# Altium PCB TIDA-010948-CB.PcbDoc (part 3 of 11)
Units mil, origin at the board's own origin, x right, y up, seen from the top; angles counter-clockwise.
Board outline 8100 x 8400 mil, 8 copper layers (L01 - TOP, L02 - GND, L03 - SIG, L04 - GND, L05 - PWR, L06 - SIG, L07 - GND, L08 - BOTTOM), stack 59.656 mil thick; 711 components, 572 nets, 2646 pads, 1325 vias.
Unrouted connection lines stored in the file: 988.
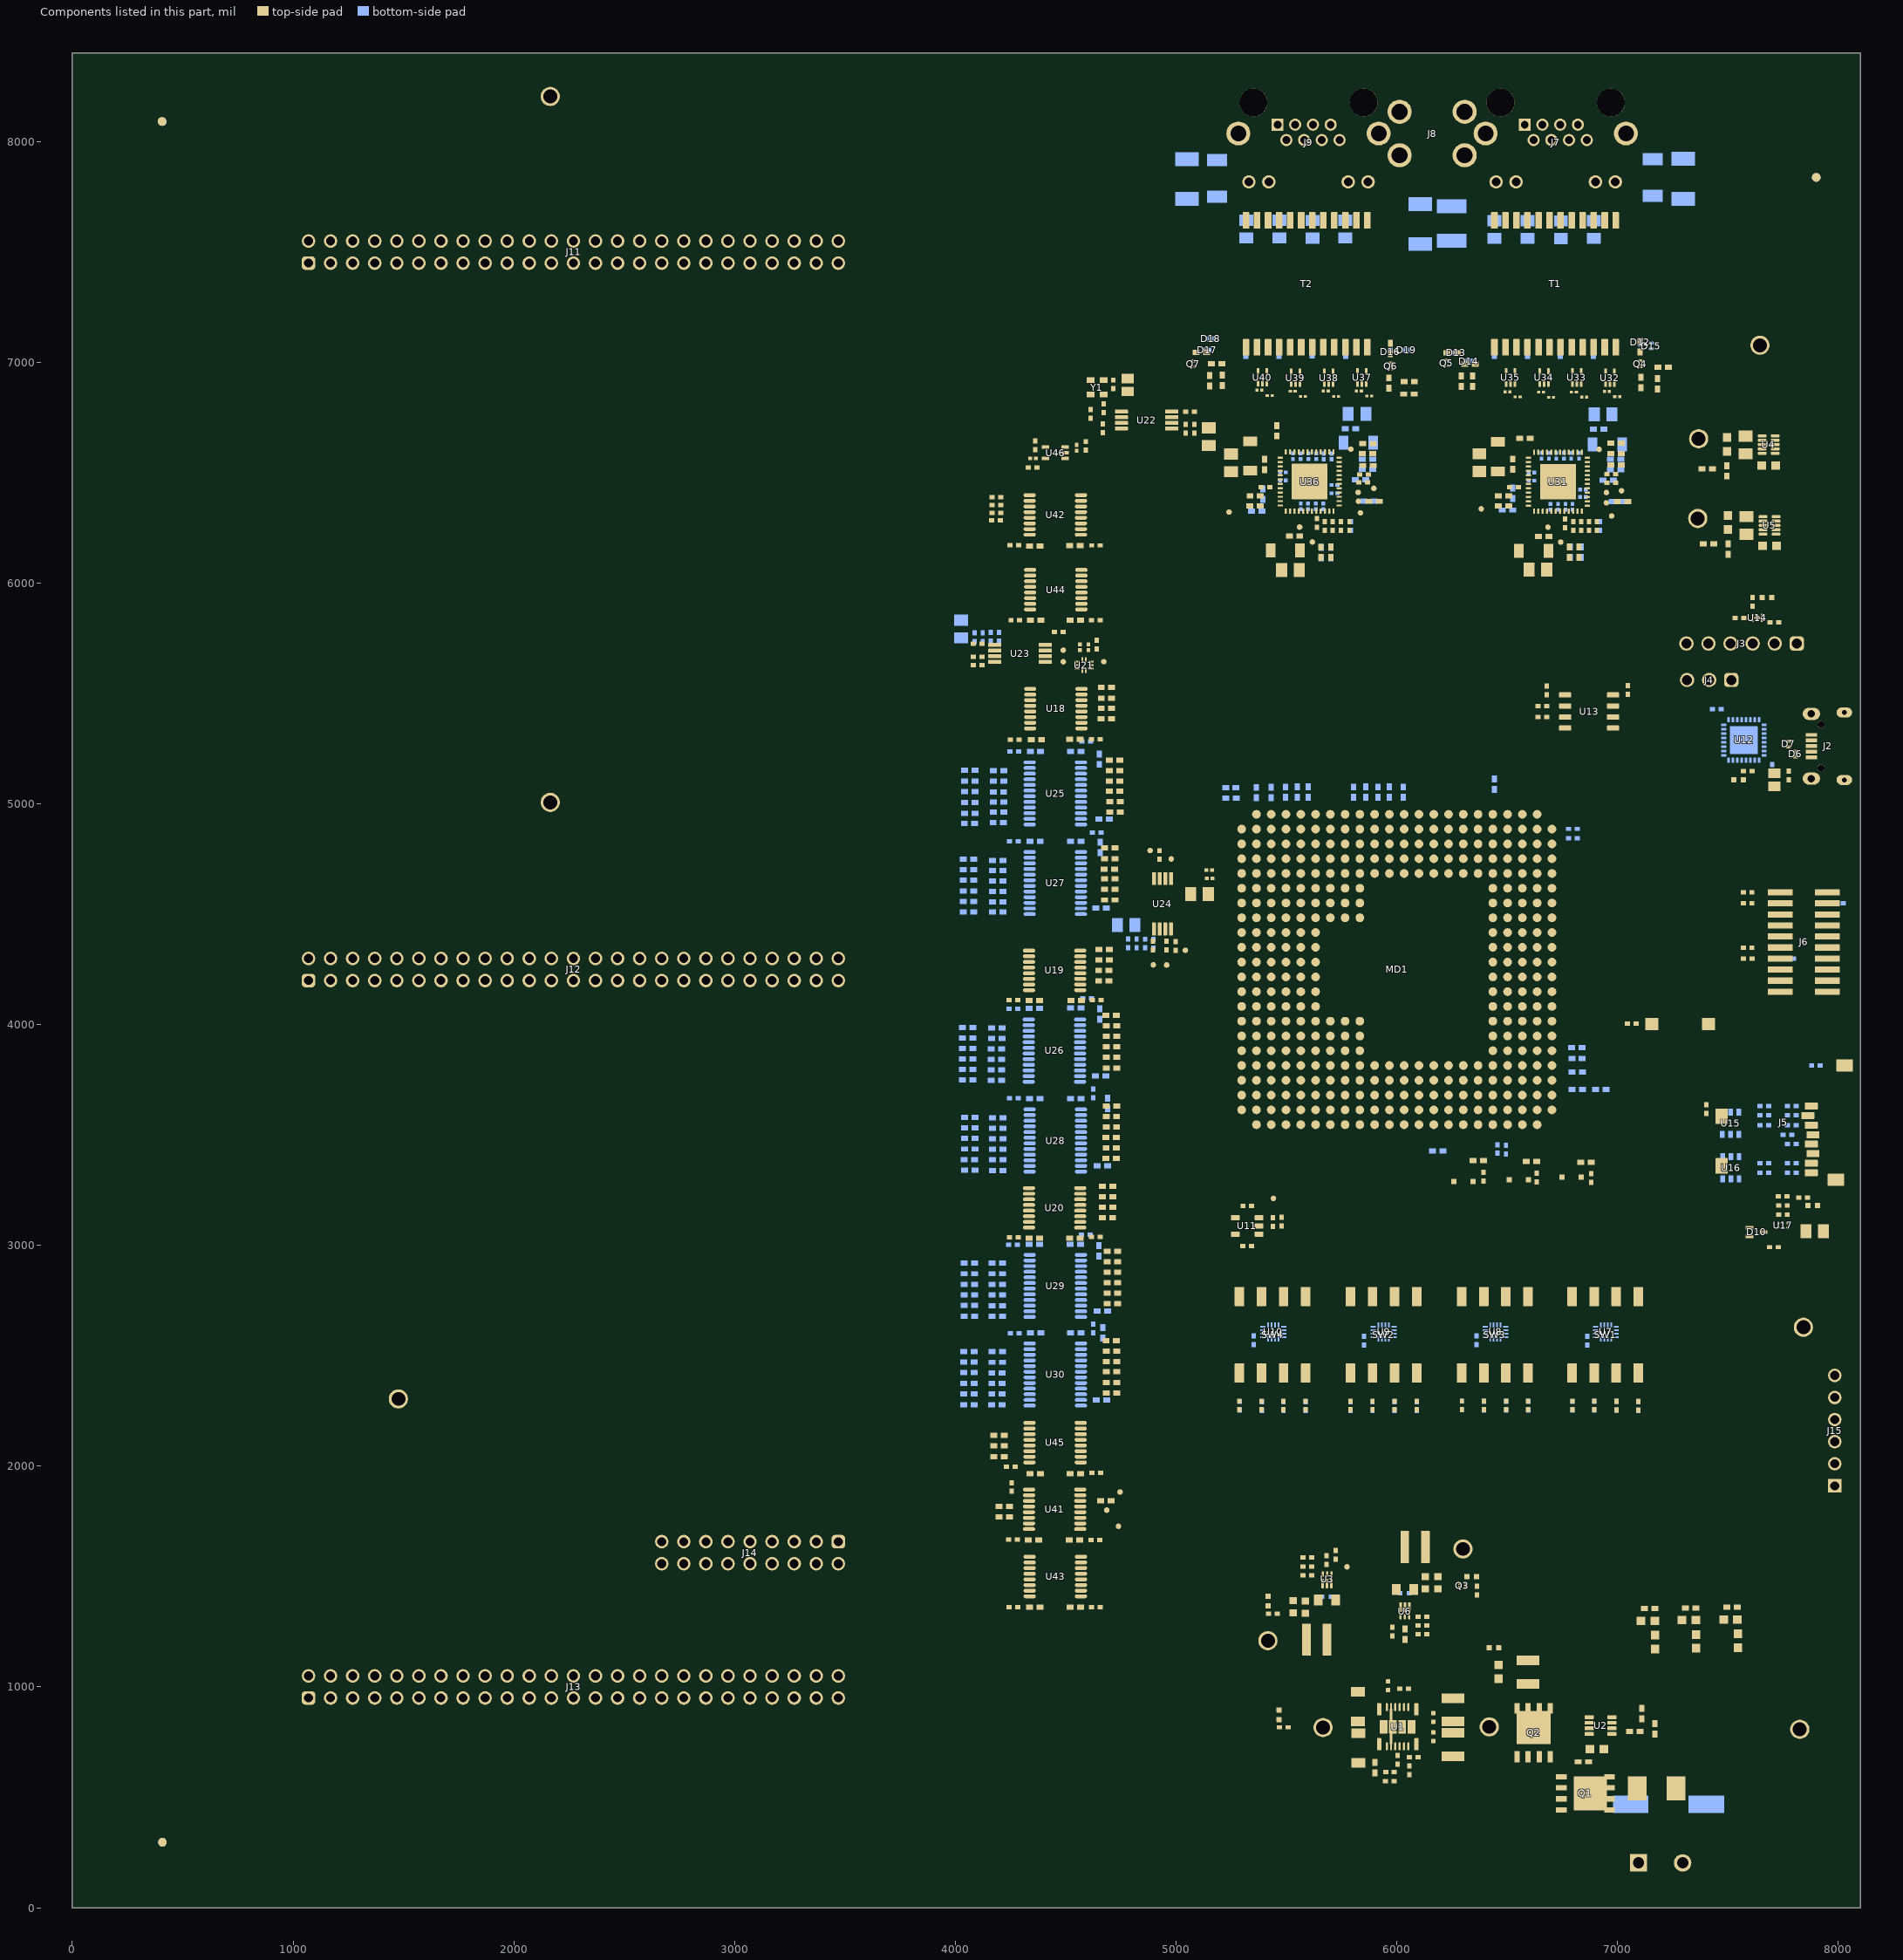
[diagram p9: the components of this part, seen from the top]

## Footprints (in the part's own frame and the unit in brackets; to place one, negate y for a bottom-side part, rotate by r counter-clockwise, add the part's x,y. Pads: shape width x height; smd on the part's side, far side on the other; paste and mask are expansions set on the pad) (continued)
0201L [mm] "Data from Kemet datasheet CC101_COM dated 7/28/11"
  rect 0.36x0.32 smd mask+0.048: 1(-0.28,0) 2(0.28,0)
  body extent -0.31,-0.16 0.31,0.16, height 0.26
0402 [mm] "0402 from SM-752 data"
  rect 0.8x0.6 smd: 1(-0.6,0) 2(0.6,0)
  silkscreen extent -1.22,-0.52 1.22,0.52, body extent -0.55,-0.3 0.55,0.3, height 0.6
0402L [mm] "0402 from SM-752 data"
  rect 0.6x0.5 smd: 1(-0.5,0) 2(0.5,0)
  body extent -0.55,-0.3 0.55,0.3, height 0.6
0603 [mm] "0603 from SM-752 data"
  rect 1x0.95 smd: 1(-0.8,0) 2(0.8,0)
  silkscreen extent -1.52,-0.69 1.52,0.69, body extent -0.87,-0.47 0.87,0.47, height 1
0603L [mm] "0603 from SM-752 data"
  rect 0.8x0.85 smd: 1(-0.7,0) 2(0.7,0)
  silkscreen extent -0.07,-0.33 0.07,0.33, body extent -0.87,-0.47 0.87,0.47, height 1
0805_HV [mil] "0805 with 30mil clearance between pads"
  rect 50x63 smd: 1(-40,0) 2(40,0)
  silkscreen extent -74,-40 74,40, body extent -43,-29 43,29, height 57
0805_HV1 [mm] "Custom footprint based on analyzing multiple manufacturer recommendations"
  rrect10% 1x1.25 smd: 1(-1,0) 2(1,0)
  silkscreen extent -0.2,-0.75 0.2,0.75, body extent -1.1,-0.72 1.1,0.73, height 1.45
0805L [mm] "0805 from SM-752 data"
  rect 1.1x1.4 smd: 1(-0.75,0) 2(0.75,0)
  body extent -1.1,-0.72 1.1,0.72, height 1.45
1206_190 [mm] "1206_190"
  rect 1.1x1.6 smd: 1(-1.7,0) 2(1.7,0)
  silkscreen extent -0.9,-1 0.9,1, body extent -1.75,-0.95 1.75,0.95, height 1.9
1210_270L [mm] "1210"
  rect 1.1x2.6 smd: 1(-1.35,0) 2(1.35,0)
  silkscreen extent -0.4,-1.2 0.4,1.2, body extent -1.7,-1.35 1.7,1.35, height 2.7
1808 [mm] "Chip Capacitor, Body 4.6x2.0mm, IPC Medium Density"
  rect 1.4x2.3 smd: 1(-2.1,0) 2(2.1,0)
  silkscreen extent -3.1,-1.45 3.1,1.45, body extent -2.47,-1.2 2.47,1.2, height 2.03
1812 [mm]
  rect 1.6x3.4 smd: 1(-2,0) 2(2,0)
  silkscreen extent -0.8,-1.6 0.8,1.6, body extent -2.4,-1.7 2.4,1.7, height 1.35
2010 [mm] "Chip Capacitor, Body 5.08x2.54mm, IPC Medium Density"
  rect 1.6x2.7 smd: 1(-2.3,0) 2(2.3,0)
  silkscreen extent -3.42,-1.65 3.42,1.65, body extent -2.73,-1.45 2.73,1.45, height 1.66
D0008B_HV [mm] "SOIC, 8-Leads, Body 4.9x3.9mm, Pitch 1.27mm, HV / Isolation option"
  rrect17% 1.4x0.6 smd: 1(-2.75,1.905) 2(-2.75,0.635) 3(-2.75,-0.635) 4(-2.75,-1.905) 5(2.75,-1.905) 6(2.75,-0.635) 7(2.75,0.635) 8(2.75,1.905)
  silkscreen extent -3.3,-2.5 0.9,2.5, body extent -3,-2.45 3,2.45, height 1.63
DBV0005A_N [mm] "SOT23, 5-Leads, Body 2.9x1.6mm, Pitch 0.95mm, Lead Span 2.8mm, IPC Medium Density"
  rrect17% 1x0.6 smd: 1(-1.375,0.95) 2(-1.375,0) 3(-1.375,-0.95) 4(1.375,-0.95) 5(1.375,0.95)
  silkscreen extent -1.63,-1.55 0.38,1.55, body extent -1.42,-1.46 1.42,1.46, height 1.09
DBV0006A_L [mm] "SOT23, 6-Leads, Body 2.9x1.6mm, Pitch 0.95mm, Lead Span 2.8mm, IPC High Density"
  rrect18% 0.8x0.55 smd: 1(-1.275,0.95) 2(-1.275,0) 3(-1.275,-0.95) 4(1.275,-0.95) 5(1.275,0) 6(1.275,0.95)
  silkscreen extent -1.55,-1.53 0.55,1.53, body extent -1.42,-1.46 1.42,1.46, height 1.12
DCK0005A_N [mm] "SOT353, 5-Leads, Body 2x1.3mm, Pitch 0.65mm, Lead Span 2.1mm, IPC Medium Density"
  rrect25% 0.85x0.4 smd: 1(-1.125,0.65) 2(-1.125,0) 3(-1.125,-0.65) 4(1.125,-0.65) 5(1.125,0.65)
  silkscreen extent -1.48,-1.02 0.55,1.1, body extent -1.14,-1 1.14,1, height 0.95
DDF0008A-MFG [mm]
  rrect22% 1.05x0.45 smd paste+0 mask+0: 1(-1.3,0.975) 2(-1.3,0.325) 3(-1.3,-0.325) 4(-1.3,-0.975) 5(1.3,-0.975) 6(1.3,-0.325) 7(1.3,0.325) 8(1.3,0.975)
  silkscreen extent -2.5,-1.48 0.4,1.48, body extent -1.92,-1.73 1.92,1.73, height 0.25
DLF0004A-MFG [mm]
  rrect15% 0.9x0.65 smd paste-1000 mask+0: 1(-0.75,0.825) 2(-0.75,-0.825) 3(0.75,-0.825) 4(0.75,0.825)
  silkscreen extent -1.87,-0.13 1.05,0.95, body extent -1.3,-1.4 1.3,1.4, height 0.25
DMQ0006A [mm] "6-pin VSON"
  rrect40% 0.6x0.25 smd paste+0: 1(-0.65,0.5) 2(-0.65,0) 3(-0.65,-0.5)
  rrect67% 1.1x0.3 smd paste-0.15 mask-0.05: 4(0.45,-0.5) 5(0.45,0) 6(0.45,0.5)
  rrect50% 0.85x0.2 on Top Paste: 4(0.525,-0.5) 5(0.525,0) 6(0.525,0.5)
  silkscreen extent -0.75,-0.9 0.75,0.9, body extent -0.75,-0.75 0.75,0.75, height 1
DPY0002A#1 [mm] "X1SON-2"
  rrect57% 0.35x0.6 smd paste-0.5 mask-0.05: 1(-0.325,0) 2(0.325,0)
  rrect33% 0.3x0.5 on Top Paste: 1S(-0.35,0) 2S(0.35,0)
  silkscreen extent -0.85,-0.02 -0.8,0.03, body extent -0.5,-0.3 0.5,0.3, height 0.45
DPY0002A#2 [mm] "X1SON-2"
  rrect57% 0.35x0.6 smd paste-0.5 mask-0.05: 1(-0.325,0) 2(0.325,0)
  rrect33% 0.3x0.5 on Bottom Paste: 1S(-0.35,0) 2S(0.35,0)
  silkscreen extent -0.85,-0.02 -0.8,0.03, body extent -0.5,-0.3 0.5,0.3, height 0.45
DQN0004A [mm] "SON, 0.65mm pitch"
  rect 0.25x0.31 smd paste-1 mask-0.31: 1(-0.535,0.325) 2(-0.535,-0.325) 3(0.535,-0.325) 4(0.535,0.325)
  rect 0.58x0.58 smd rot 45 paste-0.065 mask-0.05: 5(0,0)
  L01 - TOP region: -0.66,-0.48 -0.2,-0.48 -0.2,-0.379 -0.409,-0.17 -0.66,-0.17
  L01 - TOP region: 0.66,-0.48 0.2,-0.48 0.2,-0.379 0.409,-0.17 0.66,-0.17
  L01 - TOP region: 0.66,0.48 0.2,0.48 0.2,0.379 0.409,0.17 0.66,0.17
  L01 - TOP region: -0.66,0.48 -0.2,0.48 -0.2,0.379 -0.409,0.17 -0.66,0.17
  silkscreen extent -0.88,-0.7 0.88,0.7, body extent -0.53,-0.53 0.53,0.53, height 0.42
DRL0005A [mm] "SOTFL, 5-Flat Leads, Body 1.2x1.6x0.6mm, Pitch 0.5mm, TI recommended"
  rrect33% 0.67x0.3 smd: 1(-0.74,0.5) 2(-0.74,0) 3(-0.74,-0.5) 4(0.74,-0.5) 5(0.74,0.5)
  silkscreen extent -0.9,-0.95 0.5,0.95, body extent -0.85,-0.85 0.85,0.85, height 0.62
FCC_disclaimer [mil]
Fiducial10-20 [mm]
  round 1 smd mask+0.5: 1(0,0)
  L01 - TOP keep-out circle w1.178: c0,0 r0.5
FP-1888687_HDR2-MFG [mm]
  rrect5% 2x2 hole 1.3 paste-2539.97 mask+0: 1(-2.54,0)
  round 2 hole 1.3 paste-2539.97 mask+0: 2(2.54,0)
  body extent -5.26,-4.92 5.26,4.92, height 0.25
FP-749020011A_SMT_17MM5_14MM2-MFG [mil]
  rrect13% 29.92x75 smd paste+0 mask+0: 1(-275,-287.5) 2(-225,-287.5) 3(-175,-287.5) 4(-125,-287.5) 5(-75,-287.5) 6(-25,-287.5) 7(25,-287.5) 8(75,-287.5) 9(125,-287.5) 10(175,-287.5) 11(225,-287.5) 12(275,-287.5) 13(275,287.5) 14(225,287.5) 15(175,287.5) 16(125,287.5) 17(75,287.5) 18(25,287.5) 19(-25,287.5) 20(-75,287.5) 21(-125,287.5) 22(-175,287.5) 23(-225,287.5) 24(-275,287.5)
  body extent -353,-329 353,329, height 10
FP-418121270804_SMT_SW_11MM1_6MM2-MFG [mm]
  rrect9% 1.1x2.2 smd paste+0 mask+0: 1(-3.81,-4.4) 2(-1.27,-4.4) 3(1.27,-4.4) 4(3.81,-4.4) 5(3.81,4.4) 6(1.27,4.4) 7(-1.27,4.4) 8(-3.81,4.4)
  silkscreen extent -5.65,-6.2 5.65,3.15, body extent -5.75,-5.6 5.75,5.6, height 0.25
FP-615108137421R_CONN_JACK_16MM4_15MM7-MFG [mm]
  rrect7% 1.4x1.4 hole 0.9 paste-2539.97 mask+0: 1(3.57,0.09)
  round 1.4 hole 0.9 paste-2539.97 mask+0: 2(2.55,1.87) 3(1.53,0.09) 4(0.51,1.87) 5(-0.51,0.09) 6(-1.53,1.87) 7(-2.55,0.09) 8(-3.57,1.87)
  round 1.55 hole 1 paste-2539.97 mask+0: 9(6.86,6.68) 10(4.57,6.68) 11(-4.57,6.68) 12(-6.86,6.68)
  round 2.75 hole 1.8 paste-2539.97 mask+0: 13(-8.075,1.11) 14(8.075,1.11)
  round 3.2 hole 3.2 unplated paste-2539.97 mask+0: ""(-6.35,-2.45) ""(6.35,-2.45)
  body extent -11.62,-8.05 11.62,8.05, height 0.25
FP-629105150521_CONN_USB_8MM0_6MM6-MFG [mm]
  rect 0.45x1.3 smd: 1(-1.3,0) 2(-0.65,0) 3(0,0) 4(0.65,0) 5(1.3,0)
  oval 1.4x2 hole 0.85 slot 1.4 at 90 deg: Z1(-3.725,0) Z2(3.725,0)
  oval 1.15x1.8 hole 0.55 slot 1.2 at 90 deg: Z3(3.875,-3.8) Z4(-3.875,-3.8)
  round 0.8 hole 0.8 unplated: ""(-2.5,-1.1) ""(2.5,-1.1)
  silkscreen extent -4,-6.2 4,0.9, body extent -4,-6.25 4,0.35, height 2.67
FP-744383560047HT_1616-MFG [mm]
  rrect10% 0.98x3.7 smd paste+0 mask+0: 1(-1.185,0) 2(1.185,0)
  L01 - TOP keep-out region: -0.695,-1.85 0.695,-1.85 0.695,1.85 -0.695,1.85
  silkscreen extent -2.75,-2.15 2.15,2.15, body extent -2.25,-2.25 2.25,2.25, height 0.25
FP-885012205086_0402-MFG [mm]
  rrect20% 0.5x0.5 smd paste+0 mask+0: 1(-0.5,0) 2(0.5,0)
  silkscreen extent -0.6,-0.63 0.6,0.63, body extent -0.85,-0.45 0.85,0.45, height 0.25
FP-TQMa2434L-AA_LGA366-MFG [mm]
  round 1 smd paste+0 mask+0: A2(-16.15,17.85) A3(-14.45,17.85) A4(-12.75,17.85) A5(-11.05,17.85) A6(-9.35,17.85) A7(-7.65,17.85) A8(-5.95,17.85) A9(-4.25,17.85) A10(-2.55,17.85) A11(-0.85,17.85) A12(0.85,17.85) A13(2.55,17.85) A14(4.25,17.85) A15(5.95,17.85) A16(7.65,17.85) A17(9.35,17.85) A18(11.05,17.85) A19(12.75,17.85) A20(14.45,17.85) A21(16.15,17.85) AA1(-17.85,-16.15) AA2(-16.15,-16.15) AA3(-14.45,-16.15) AA4(-12.75,-16.15) AA5(-11.05,-16.15) AA6(-9.35,-16.15) AA7(-7.65,-16.15) AA8(-5.95,-16.15) AA9(-4.25,-16.15) AA10(-2.55,-16.15) AA11(-0.85,-16.15) AA12(0.85,-16.15) AA13(2.55,-16.15) AA14(4.25,-16.15) AA15(5.95,-16.15) AA16(7.65,-16.15) AA17(9.35,-16.15) AA18(11.05,-16.15) AA19(12.75,-16.15) AA20(14.45,-16.15) AA21(16.15,-16.15) AA22(17.85,-16.15) AB2(-16.15,-17.85) AB3(-14.45,-17.85) AB4(-12.75,-17.85) AB5(-11.05,-17.85) AB6(-9.35,-17.85) AB7(-7.65,-17.85) AB8(-5.95,-17.85) AB9(-4.25,-17.85) AB10(-2.55,-17.85) AB11(-0.85,-17.85) AB12(0.85,-17.85) AB13(2.55,-17.85) AB14(4.25,-17.85) AB15(5.95,-17.85) AB16(7.65,-17.85) AB17(9.35,-17.85) AB18(11.05,-17.85) AB19(12.75,-17.85) AB20(14.45,-17.85) AB21(16.15,-17.85) B1(-17.85,16.15) B2(-16.15,16.15) B3(-14.45,16.15) B4(-12.75,16.15) B5(-11.05,16.15) B6(-9.35,16.15) B7(-7.65,16.15) B8(-5.95,16.15) B9(-4.25,16.15) B10(-2.55,16.15) B11(-0.85,16.15) B12(0.85,16.15) B13(2.55,16.15) B14(4.25,16.15) B15(5.95,16.15) B16(7.65,16.15) B17(9.35,16.15) B18(11.05,16.15) B19(12.75,16.15) B20(14.45,16.15) B21(16.15,16.15) B22(17.85,16.15) C1(-17.85,14.45) C2(-16.15,14.45) C3(-14.45,14.45) C4(-12.75,14.45) C5(-11.05,14.45) C6(-9.35,14.45) C7(-7.65,14.45) C8(-5.95,14.45) C9(-4.25,14.45) C10(-2.55,14.45) C11(-0.85,14.45) C12(0.85,14.45) C13(2.55,14.45) C14(4.25,14.45) C15(5.95,14.45) C16(7.65,14.45) C17(9.35,14.45) C18(11.05,14.45) C19(12.75,14.45) C20(14.45,14.45) C21(16.15,14.45) C22(17.85,14.45) D1(-17.85,12.75) D2(-16.15,12.75) D3(-14.45,12.75) D4(-12.75,12.75) D5(-11.05,12.75) D6(-9.35,12.75) D7(-7.65,12.75) D8(-5.95,12.75) D9(-4.25,12.75) D10(-2.55,12.75) D11(-0.85,12.75) D12(0.85,12.75) D13(2.55,12.75) D14(4.25,12.75) D15(5.95,12.75) D16(7.65,12.75) D17(9.35,12.75) D18(11.05,12.75) D19(12.75,12.75) D20(14.45,12.75) D21(16.15,12.75) D22(17.85,12.75) E1(-17.85,11.05) E2(-16.15,11.05) E3(-14.45,11.05) E4(-12.75,11.05) E5(-11.05,11.05) E6(-9.35,11.05) E7(-7.65,11.05) E8(-5.95,11.05) E9(-4.25,11.05) E10(-2.55,11.05) E11(-0.85,11.05) E12(0.85,11.05) E13(2.55,11.05) E14(4.25,11.05) E15(5.95,11.05) E16(7.65,11.05) E17(9.35,11.05) E18(11.05,11.05) E19(12.75,11.05) E20(14.45,11.05) E21(16.15,11.05) E22(17.85,11.05) F1(-17.85,9.35) F2(-16.15,9.35) F3(-14.45,9.35) F4(-12.75,9.35) F5(-11.05,9.35) F6(-9.35,9.35) F7(-7.65,9.35) F8(-5.95,9.35) F9(-4.25,9.35) F18(11.05,9.35) F19(12.75,9.35) F20(14.45,9.35) F21(16.15,9.35) F22(17.85,9.35) G1(-17.85,7.65) G2(-16.15,7.65) G3(-14.45,7.65) G4(-12.75,7.65) G5(-11.05,7.65) G6(-9.35,7.65) G7(-7.65,7.65) G8(-5.95,7.65) G9(-4.25,7.65) G18(11.05,7.65) G19(12.75,7.65) G20(14.45,7.65) G21(16.15,7.65) G22(17.85,7.65) H1(-17.85,5.95) H2(-16.15,5.95) H3(-14.45,5.95) H4(-12.75,5.95) H5(-11.05,5.95) H6(-9.35,5.95) H7(-7.65,5.95) H8(-5.95,5.95) H9(-4.25,5.95) H18(11.05,5.95) H19(12.75,5.95) H20(14.45,5.95) H21(16.15,5.95) H22(17.85,5.95) J1(-17.85,4.25) J2(-16.15,4.25) J3(-14.45,4.25) J4(-12.75,4.25) J5(-11.05,4.25) J6(-9.35,4.25) J18(11.05,4.25) J19(12.75,4.25) J20(14.45,4.25) J21(16.15,4.25) J22(17.85,4.25) K1(-17.85,2.55) K2(-16.15,2.55) K3(-14.45,2.55) K4(-12.75,2.55) K5(-11.05,2.55) K6(-9.35,2.55) K18(11.05,2.55) K19(12.75,2.55) K20(14.45,2.55) K21(16.15,2.55) K22(17.85,2.55) L1(-17.85,0.85) L2(-16.15,0.85) L3(-14.45,0.85) L4(-12.75,0.85) L5(-11.05,0.85) L6(-9.35,0.85) L18(11.05,0.85) L19(12.75,0.85) L20(14.45,0.85) L21(16.15,0.85) L22(17.85,0.85) M1(-17.85,-0.85) M2(-16.15,-0.85) M3(-14.45,-0.85) M4(-12.75,-0.85) M5(-11.05,-0.85) M6(-9.35,-0.85) M18(11.05,-0.85) M19(12.75,-0.85) M20(14.45,-0.85) M21(16.15,-0.85) M22(17.85,-0.85) N1(-17.85,-2.55) N2(-16.15,-2.55) N3(-14.45,-2.55) N4(-12.75,-2.55) N5(-11.05,-2.55) N6(-9.35,-2.55) N18(11.05,-2.55) N19(12.75,-2.55) N20(14.45,-2.55) N21(16.15,-2.55) N22(17.85,-2.55) P1(-17.85,-4.25) P2(-16.15,-4.25) P3(-14.45,-4.25) P4(-12.75,-4.25) P5(-11.05,-4.25) P6(-9.35,-4.25) P18(11.05,-4.25) P19(12.75,-4.25) P20(14.45,-4.25) P21(16.15,-4.25) P22(17.85,-4.25) R1(-17.85,-5.95) R2(-16.15,-5.95) R3(-14.45,-5.95) R4(-12.75,-5.95) R5(-11.05,-5.95) R6(-9.35,-5.95) R7(-7.65,-5.95) R8(-5.95,-5.95) R9(-4.25,-5.95) R18(11.05,-5.95) R19(12.75,-5.95) R20(14.45,-5.95) R21(16.15,-5.95) R22(17.85,-5.95) T1(-17.85,-7.65) T2(-16.15,-7.65) T3(-14.45,-7.65) T4(-12.75,-7.65) T5(-11.05,-7.65) T6(-9.35,-7.65) T7(-7.65,-7.65) T8(-5.95,-7.65) T9(-4.25,-7.65) T18(11.05,-7.65) T19(12.75,-7.65) T20(14.45,-7.65) T21(16.15,-7.65) T22(17.85,-7.65) U1(-17.85,-9.35) U2(-16.15,-9.35) U3(-14.45,-9.35) U4(-12.75,-9.35) U5(-11.05,-9.35) U6(-9.35,-9.35) U7(-7.65,-9.35) U8(-5.95,-9.35) U9(-4.25,-9.35) U18(11.05,-9.35) U19(12.75,-9.35) U20(14.45,-9.35) U21(16.15,-9.35) U22(17.85,-9.35) V1(-17.85,-11.05) V2(-16.15,-11.05) V3(-14.45,-11.05) V4(-12.75,-11.05) V5(-11.05,-11.05) V6(-9.35,-11.05) V7(-7.65,-11.05) V8(-5.95,-11.05) V9(-4.25,-11.05) V10(-2.55,-11.05) V11(-0.85,-11.05) V12(0.85,-11.05) V13(2.55,-11.05) V14(4.25,-11.05) V15(5.95,-11.05) V16(7.65,-11.05) V17(9.35,-11.05) V18(11.05,-11.05) V19(12.75,-11.05) V20(14.45,-11.05) V21(16.15,-11.05) V22(17.85,-11.05) W1(-17.85,-12.75) W2(-16.15,-12.75) W3(-14.45,-12.75) W4(-12.75,-12.75) W5(-11.05,-12.75) W6(-9.35,-12.75) W7(-7.65,-12.75) W8(-5.95,-12.75) W9(-4.25,-12.75) W10(-2.55,-12.75) W11(-0.85,-12.75) W12(0.85,-12.75) W13(2.55,-12.75) W14(4.25,-12.75) W15(5.95,-12.75) W16(7.65,-12.75) W17(9.35,-12.75) W18(11.05,-12.75) W19(12.75,-12.75) W20(14.45,-12.75) W21(16.15,-12.75) W22(17.85,-12.75) Y1(-17.85,-14.45) Y2(-16.15,-14.45) Y3(-14.45,-14.45) Y4(-12.75,-14.45) Y5(-11.05,-14.45) Y6(-9.35,-14.45) Y7(-7.65,-14.45) Y8(-5.95,-14.45) Y9(-4.25,-14.45) Y10(-2.55,-14.45) Y11(-0.85,-14.45) Y12(0.85,-14.45) Y13(2.55,-14.45) Y14(4.25,-14.45) Y15(5.95,-14.45) Y16(7.65,-14.45) Y17(9.35,-14.45) Y18(11.05,-14.45) Y19(12.75,-14.45) Y20(14.45,-14.45) Y21(16.15,-14.45) Y22(17.85,-14.45)
  Keep-Out Layer board cut-out: -2.9,8.9 -2.824,9.283 -2.607,9.607 -2.283,9.824 -1.9,9.9 -1.9,9.9 8.9,9.9 9.283,9.824 9.607,9.607 9.824,9.283 9.9,8.9 9.9,8.9 9.9,-8.9 9.824,-9.283 9.607,-9.607 9.283,-9.824 8.9,-9.9 8.9,-9.9 -1.9,-9.9 -2.283,-9.824 -2.607,-9.607 -2.824,-9.283 -2.9,-8.9 -2.9,-8.9
  silkscreen extent -19.77,-19.05 19.05,19.05, body extent -19.55,-19.55 19.55,19.55, height 0.25
Keystone5129 [mil] "Keystone Multipurpose loops"
  round 87 hole 63: 1(0,0)
  silkscreen extent -70,-70 70,70, body extent -63,-63 63,62, height 319
Keystone_7781 [mm] "Terminal screw, R/A"
  round 2.775 hole 1.85: 1(-2.5,3.745) 2(2.5,3.745) 3(-2.5,-3.745) 4(2.5,-3.745)
  silkscreen extent 4.2,-4.3 7.58,4.3, body extent -3.95,-4.71 7.57,4.71, height 7.92
Label_650x200 [mil] "Thermal Transfer Label"
  round 1 on Mech13: 0(0,0)
  silkscreen extent -325,-100 325,100, body extent -325,-100 325,100, height 1
Molex_693071010811 [mm] "MicroSD Card Connector, R/A, SMT"
  rrect12% 0.8x1.5 smd: 1(-1.942,3.1) 2(-0.842,2.7) 3(0.258,3.1) 4(1.358,3.3) 5(2.458,3.1) 6(3.558,3.3) 7(4.658,3.1) 8(5.758,3.1)
  rrect7% 1.4x1.9 smd: 9(-6.602,6.95) 9(6.548,5.95)
  rrect7% 1.8x1.4 smd: 10(-0.752,-7.2) 10(4.948,-7.2)
  silkscreen extent -6.99,-7.6 7.01,7.6, body extent -7,-7.6 7,7.6, height 1.83
Net-Tie_10milWide_30milLong [mil] "10mil net tie, no solder mask opening, no solder paste"
  rect 30x10 smd paste-5 mask-5: 1(-15,0) 2(15,0)
NetTie_0402 [mm] "Net Tie 0402 size"
  rect 0.6x0.5 smd paste-0.5: 1(-0.5,0) 2(0.5,0)
  L01 - TOP region: -0.279,0.203 0.279,0.203 0.279,-0.203 -0.279,-0.203
PowerPAK_SO-8 [mil] "Vishay PowerPAK SO-8, Body 5.3x6.0mm (max), Pitch 1.27mm, IPC Medium Density"
  rect 50x24 smd mask+2.99: 1(-109.5,75) 2(-109.5,25) 3(-109.5,-25) 4(-109.5,-75)
  rect 48x24 smd mask+2.99: 5(109.5,-75) 8(109.5,75)
  rect 48x24 smd paste-12 mask+2.99: 6(109.5,-25) 7(109.5,25)
  rect 150x154 smd paste-75 mask+2.99: 9(22.5,0)
  silkscreen extent -130,-104 59,104, body extent -121,-102 121,102, height 43
PW0008A-MFG [mm]
  rrect22% 1.5x0.45 smd paste+0 mask+0: 1(-2.9,0.975) 2(-2.9,0.325) 3(-2.9,-0.325) 4(-2.9,-0.975) 5(2.9,-0.975) 6(2.9,-0.325) 7(2.9,0.325) 8(2.9,0.975)
  silkscreen extent -4.37,-1.55 1.77,1.55, body extent -3.75,-1.8 3.75,1.8, height 0.25
PW0016A_N [mm] "TSOP, 16-Leads, Body 5x4.4mm, Pitch 0.65mm, IPC Medium Density"
  oval 1.4x0.45 smd: 1(-2.95,2.275) 2(-2.95,1.625) 3(-2.95,0.975) 4(-2.95,0.325) 5(-2.95,-0.325) 6(-2.95,-0.975) 7(-2.95,-1.625) 8(-2.95,-2.275) 9(2.95,-2.275) 10(2.95,-1.625) 11(2.95,-0.975) 12(2.95,-0.325) 13(2.95,0.325) 14(2.95,0.975) 15(2.95,1.625) 16(2.95,2.275)
  silkscreen extent -3.5,-2.55 1.85,2.75, body extent -3.21,-2.5 3.21,2.5, height 1
PW0024A_N [mm] "TSOP, 24-Leads, Body 7.8x4.4mm, Pitch 0.65mm, IPC Medium Density"
  oval 1.4x0.45 smd: 1(-2.95,3.575) 2(-2.95,2.925) 3(-2.95,2.275) 4(-2.95,1.625) 5(-2.95,0.975) 6(-2.95,0.325) 7(-2.95,-0.325) 8(-2.95,-0.975) 9(-2.95,-1.625) 10(-2.95,-2.275) 11(-2.95,-2.925) 12(-2.95,-3.575) 13(2.95,-3.575) 14(2.95,-2.925) 15(2.95,-2.275) 16(2.95,-1.625) 17(2.95,-0.975) 18(2.95,-0.325) 19(2.95,0.325) 20(2.95,0.975) 21(2.95,1.625) 22(2.95,2.275) 23(2.95,2.925) 24(2.95,3.575)
  silkscreen extent -3.51,-3.95 1.6,4.04, body extent -3.21,-3.9 3.21,3.9, height 1
QFN32-5x5MM [mm] "QFN, 32-Leads, Body 5x5mm, Pitch 0.5mm"
  rrect33% 0.6x0.3 smd: 1(-2.325,1.75) 2(-2.325,1.25) 3(-2.325,0.75) 4(-2.325,0.25) 5(-2.325,-0.25) 6(-2.325,-0.75) 7(-2.325,-1.25) 8(-2.325,-1.75) 17(2.325,-1.75) 18(2.325,-1.25) 19(2.325,-0.75) 20(2.325,-0.25) 21(2.325,0.25) 22(2.325,0.75) 23(2.325,1.25) 24(2.325,1.75)
  rrect33% 0.3x0.6 smd: 9(-1.75,-2.325) 10(-1.25,-2.325) 11(-0.75,-2.325) 12(-0.25,-2.325) 13(0.25,-2.325) 14(0.75,-2.325) 15(1.25,-2.325) 16(1.75,-2.325) 25(1.75,2.325) 26(1.25,2.325) 27(0.75,2.325) 28(0.25,2.325) 29(-0.25,2.325) 30(-0.75,2.325) 31(-1.25,2.325) 32(-1.75,2.325)
  rrect3% 3.2x3.2 smd paste-3.2: 33(0,0)
  silkscreen extent -2.65,-2.65 2.65,2.65, body extent -2.54,-2.54 2.54,2.54, height 1.01
RDL0020A-MFG [mm]
  rrect20% 1.4x0.5 smd paste-1000 mask+0: 1(-2,2.175) 8(-2,-2.125) 9(2,-2.125) 16(2,2.175)
  rrect40% 0.9x0.25 smd paste-1000 mask+0: 2(-2.25,1.25) 3(-2.25,0.75) 4(-2.25,0.25) 5(-2.25,-0.25) 6(-2.25,-0.75) 7(-2.25,-1.25) 10(2.25,-1.25) 11(2.25,-0.75) 12(2.25,-0.25) 13(2.25,0.25) 14(2.25,0.75) 15(2.25,1.25)
  rrect11% 1.58x0.875 smd paste-1000 mask+0: 17(0,1.613) 18(0,0.538) 19(0,-0.538) 20(0,-1.613)
  silkscreen extent -3.37,-2.9 2.55,2.9, body extent -2.8,-2.9 2.8,2.9, height 0.25
RGZ0048B-MFG [mm]
  rrect42% 0.6x0.24 smd paste+0 mask+0: 1(-3.4,2.75) 2(-3.4,2.25) 3(-3.4,1.75) 4(-3.4,1.25) 5(-3.4,0.75) 6(-3.4,0.25) 7(-3.4,-0.25) 8(-3.4,-0.75) 9(-3.4,-1.25) 10(-3.4,-1.75) 11(-3.4,-2.25) 12(-3.4,-2.75) 25(3.4,-2.75) 26(3.4,-2.25) 27(3.4,-1.75) 28(3.4,-1.25) 29(3.4,-0.75) 30(3.4,-0.25) 31(3.4,0.25) 32(3.4,0.75) 33(3.4,1.25) 34(3.4,1.75) 35(3.4,2.25) 36(3.4,2.75)
  rrect42% 0.24x0.6 smd paste+0 mask+0: 13(-2.75,-3.4) 14(-2.25,-3.4) 15(-1.75,-3.4) 16(-1.25,-3.4) 17(-0.75,-3.4) 18(-0.25,-3.4) 19(0.25,-3.4) 20(0.75,-3.4) 21(1.25,-3.4) 22(1.75,-3.4) 23(2.25,-3.4) 24(2.75,-3.4) 37(2.75,3.4) 38(2.25,3.4) 39(1.75,3.4) 40(1.25,3.4) 41(0.75,3.4) 42(0.25,3.4) 43(-0.25,3.4) 44(-0.75,3.4) 45(-1.25,3.4) 46(-1.75,3.4) 47(-2.25,3.4) 48(-2.75,3.4)
  rrect2% 4.1x4.1 smd paste-1000 mask+0: 49(0,0)
  silkscreen extent -4.37,-3.57 3.57,3.57, body extent -3.8,-3.8 3.8,3.8, height 0.25
RSV0016A [mm] "QFN, 16-Leads, Body 1.8x2.6mm, Pitch 0.4mm, TI Recommended"
  rect 0.7x0.2 smd: 1(-0.75,0.6)
  rect 0.6x0.2 smd: 2(-0.8,0.2) 3(-0.8,-0.2) 4(-0.8,-0.6) 9(0.8,-0.6) 10(0.8,-0.2) 11(0.8,0.2) 12(0.8,0.6)
  rect 0.2x0.6 smd: 5(-0.6,-1.2) 6(-0.2,-1.2) 7(0.2,-1.2) 8(0.6,-1.2) 13(0.6,1.2) 14(0.2,1.2) 15(-0.2,1.2) 16(-0.6,1.2)
  silkscreen extent -1.08,-1.33 1.08,1.45, body extent -0.92,-1.32 0.92,1.33, height 0.56
RSW0010A [mm] "QFN, 10-Leads, Body 1.8x1.4 mm, Pitch 0.4mm, TI Recommended"
  rrect50% 0.7x0.2 smd: 1(-0.55,0.2)
  rrect50% 0.6x0.2 smd: 2(-0.6,-0.2) 6(0.6,-0.2) 7(0.6,0.2)
  rrect50% 0.2x0.6 smd: 3(-0.4,-0.8) 4(0,-0.8) 5(0.4,-0.8) 8(0.4,0.8) 9(0,0.8) 10(-0.4,0.8)
  silkscreen extent -0.88,-1.08 0.88,1.08, body extent -0.7,-0.9 0.7,0.9, height 0.56
Samtec_FTR-110-51-x-D-06 [mm] "Header, 1.27mm, 10x2, SMT"
  rect 2.87x0.711 smd: 1(-2.705,5.715) 2(2.705,5.715) 3(-2.705,4.445) 4(2.705,4.445) 5(-2.705,3.175) 6(2.705,3.175) 7(-2.705,1.905) 8(2.705,1.905) 9(-2.705,0.635) 10(2.705,0.635) 11(-2.705,-0.635) 12(2.705,-0.635) 13(-2.705,-1.905) 14(2.705,-1.905) 15(-2.705,-3.175) 16(2.705,-3.175) 17(-2.705,-4.445) 18(2.705,-4.445) 19(-2.705,-5.715) 20(2.705,-5.715)
  silkscreen extent -2.49,-6.35 2.49,6.7, body extent -3.76,-6.35 3.76,6.35, height 8.64
Samtec_TSW-109-09-x-D [mm] "Header, 2.54mm, 9x2, TH"
  rrect50% 1.55x1.55 hole 1.02: 1(-1.27,10.16)
  round 1.55 hole 1.02: 2(1.27,10.16) 3(-1.27,7.62) 4(1.27,7.62) 5(-1.27,5.08) 6(1.27,5.08) 7(-1.27,2.54) 8(1.27,2.54) 9(-1.27,0) 10(1.27,0) 11(-1.27,-2.54) 12(1.27,-2.54) 13(-1.27,-5.08) 14(1.27,-5.08) 15(-1.27,-7.62) 16(1.27,-7.62) 17(-1.27,-10.16) 18(1.27,-10.16)
  silkscreen extent -3,-11.43 2.54,11.43, body extent -2.54,-11.43 2.54,11.43, height 8.4
Samtec_TSW-125-08-x-D [mm] "Header, 2.54mm, 25x2, TH"
  rrect50% 1.55x1.55 hole 1.02: 1(-1.27,30.48)
  round 1.55 hole 1.02: 2(1.27,30.48) 3(-1.27,27.94) 4(1.27,27.94) 5(-1.27,25.4) 6(1.27,25.4) 7(-1.27,22.86) 8(1.27,22.86) 9(-1.27,20.32) 10(1.27,20.32) 11(-1.27,17.78) 12(1.27,17.78) 13(-1.27,15.24) 14(1.27,15.24) 15(-1.27,12.7) 16(1.27,12.7) 17(-1.27,10.16) 18(1.27,10.16) 19(-1.27,7.62) 20(1.27,7.62) 21(-1.27,5.08) 22(1.27,5.08) 23(-1.27,2.54) 24(1.27,2.54) 25(-1.27,0) 26(1.27,0) 27(-1.27,-2.54) 28(1.27,-2.54) 29(-1.27,-5.08) 30(1.27,-5.08) 31(-1.27,-7.62) 32(1.27,-7.62) 33(-1.27,-10.16) 34(1.27,-10.16) 35(-1.27,-12.7) 36(1.27,-12.7) 37(-1.27,-15.24) 38(1.27,-15.24) 39(-1.27,-17.78) 40(1.27,-17.78) 41(-1.27,-20.32) 42(1.27,-20.32) 43(-1.27,-22.86) 44(1.27,-22.86) 45(-1.27,-25.4) 46(1.27,-25.4) 47(-1.27,-27.94) 48(1.27,-27.94) 49(-1.27,-30.48) 50(1.27,-30.48)
  silkscreen extent -3,-31.75 2.54,31.75, body extent -2.54,-31.75 2.54,31.75, height 8.4
SIL0010D [mm] "MicoSiP, 10-Leads, Body 2x2.5mm"
  rrect57% 1x0.35 smd paste-0.05 mask-0.05: 1(-0.75,1) 2(-0.75,0.5) 3(-0.75,0) 4(-0.75,-0.5) 5(-0.75,-1) 6(0.75,-1) 7(0.75,-0.5) 8(0.75,0) 9(0.75,0.5) 10(0.75,1)
  body extent -1.05,-1.3 1.05,1.3, height 1.35
SM_RADIAL_G [mm] "10 x 10.2mm:  Panasonic G"
  rect 4.1x2 smd: 1(-4.35,0) 2(4.35,0)
  silkscreen extent -5.35,-5.35 5.35,5.35, body extent -5.25,-5.25 5.25,5.25, height 10.5
SMB-Bi [mil] "Molded Diode, 2-Leads, Body 5.4x3.6mm, IPC Medium Density, based on OnSemi component dimensions"
  rect 85x107.99 smd: 1(-87.01,0) 2(87.01,0)
  silkscreen extent -125,-79 125,79, body extent -104,-73 104,73, height 89
SOD-323 [mm] "NXP recommended land pattern"
  rect 0.6x0.6 smd paste-0.05: 1(-1.1,0) 2(1.1,0)
  silkscreen extent -2.06,-0.86 1.53,0.86, body extent -1.3,-0.67 1.3,0.68, height 1.1
SOT-523 [mm] "From Diodes Inc datasheet component parameters"
  rect 0.9x0.4 smd: 1(-0.8,0.5) 2(-0.8,-0.5) 3(0.8,0)
  silkscreen extent 0.02,-0.85 0.42,0.85, body extent -0.8,-0.8 0.8,0.8, height 0.79
Sullins_PxC06SAAN [mm] "Header, 2.54mm, 6x1, TH"
  rect 1.55x1.55 hole 1.016: 1(-6.35,0)
  round 1.55 hole 1.016: 2(-3.81,0) 3(-1.27,0) 4(1.27,0) 5(3.81,0) 6(6.35,0)
  silkscreen extent -7.62,-1.27 7.62,1.6, body extent -7.62,-1.27 7.62,1.27, height 8.38
SW_434121025816 [mm] "SMD, 2-Leads, Body 6x3.9mm, Pitch 6.5mm"
  rect 1.5x1.4 smd: 1(-3.25,0) 2(3.25,0)
  silkscreen extent -3,-1.95 3,1.95, body extent -3.65,-1.95 3.65,1.95, height 2.5
TP_25MIL-SMT [mil]
  round 25 smd mask-2.5: 1(0,0)
WEEE_Minimum [mil] "WEEElie bin"
  silkscreen extent -95,-172 99,104
WL-SMCC_0402_Green [mm] "SMD, 2-Leads, Body 1x0.5mm"
  rrect17% 0.6x0.6 smd: 1(-0.55,0) 2(0.55,0)
  body extent -0.5,-0.25 0.5,0.25, height 0.39
WURTH_61300311121 [mm] "Header, 2.54mm, 3x1, TH"
  rrect50% 1.65x1.65 hole 1.15: 1(-2.54,0)
  round 1.65 hole 1.15: 2(0,0) 3(2.54,0)
  body extent -3.81,-1.27 3.81,1.27, height 8.54
WURTH_61300611121 [mm] "Header, 2.54mm, 6x1, TH"
  rrect50% 1.65x1.65 hole 1.15: 1(-6.35,0)
  round 1.65 hole 1.15: 2(-3.81,0) 3(-1.27,0) 4(1.27,0) 5(3.81,0) 6(6.35,0)
  body extent -7.62,-1.27 7.62,1.27, height 8.54
YJC0003A [mm] "TI"
  rrect50% 0.25x0.2 on Top Paste: 0(-0.325,-0.2) 0(-0.325,0.2)
  rrect80% 0.35x0.25 smd paste-0.13 mask-0.05: 1(-0.325,0.175) 2(-0.325,-0.175)
  rrect57% 0.35x0.6 smd paste-0.05 mask-0.05: 3(0.325,0)
  body extent -0.5,-0.3 0.5,0.3, height 0.35
YZP0006AFAF [mm] "BGA, 6-Leads, Pitch 0.5mm"
  round 0.23 smd paste-0.12: A1(-0.25,0.5) A2(0.25,0.5) B1(-0.25,0) B2(0.25,0) C1(-0.25,-0.5) C2(0.25,-0.5)
  silkscreen extent -0.6,-0.82 0.6,0.85, body extent -0.49,-0.74 0.49,0.74, height 0.51

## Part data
C1 C2 C10: library part CMP-0009226-3, "CAP, CERM, 10 uF, 50 V, +/- 10%, X7R, 1210", Cap_Case=1210, Manufacturer=MuRata, Supplier Part Number 1=490-6544-1-ND, TempCo=X7R, Tolerance_%=10%, Value1=Unknown, Value2=50V, ValueDisplayed=10uF
C3: library part CMP-0011181-2, "CAP, AL, 220 uF, 50 V, +/- 20%, 0.18 ohm, AEC-Q200 Grade 2, SMD", Cap_Case=G, Manufacturer=Panasonic, Supplier Part Number 1=PCE3812CT-ND, Tolerance_%=20%, Value1="0.18 ohm", Value2=50V, ValueDisplayed=220uF
C4 C5 C8 C12 C20: library part CMP-0096737-1, "100 nF ±10% 50V Ceramic Capacitor X7R 0402 (1005 Metric)", Manufacturer=Wurth, Operating Temperature Range="-55°C to +125°C", TempCo=15%, Temperature Characteristic=X7R, Tolerance_%=10%, ValueDisplayed=100nF
C6 C7: library part CMP-0008656-2, "CAP, CERM, 47 uF, 25 V, +/- 20%, X5R, 1206_190", Cap_Case=1206, Manufacturer=TDK, Supplier Part Number 1=445-8047-1-ND, TempCo=X5R, Tolerance_%=20%, Value1=Unknown, Value2=25V, ValueDisplayed=47uF
C9 C138 C180: library part CMP-0006311-2, "CAP, CERM, 22 pF, 50 V, +/- 5%, C0G/NP0, AEC-Q200 Grade 1, 0402", Cap_Case=0402, Manufacturer=TDK, Supplier Part Number 1=445-12130-1-ND, TempCo=C0G/NP0, Tolerance_%=5%, Value1=Unknown, Value2=50V, ValueDisplayed=22pF
C11: library part CMP-0007144-4, "CAP, CERM, 0.1 uF, 50 V, +/- 10%, X7R, 0603", Cap_Case=0603, Manufacturer=MuRata, Supplier Part Number 1=490-4779-1-ND, TempCo=X7R, Tolerance_%=10%, Value1="0.02 ohm", Value2=50V, ValueDisplayed=0.1uF
C13 C21: library part CMP-0085894-1, "CAP, CERM, 10 µF, 35 V,+/- 10%, JB, 0805", Cap_Case=0805, Manufacturer=TDK, TempCo=JB, Tolerance_%=10%, Value2=35V, ValueDisplayed=10µF
C14 C25: library part CMP-0006417-2, "CAP, CERM, 120 pF, 50 V, +/- 5%, C0G/NP0, 0402", Cap_Case=0402, Manufacturer=MuRata, Supplier Part Number 1=490-1292-1-ND, TempCo=C0G/NP0, Tolerance_%=5%, Value1=Unknown, Value2=50V, ValueDisplayed=120pF
C15 C22: library part CMP-0007497-5, "CAP, CERM, 10 uF, 10 V, +/- 20%, X7R, 0603", Cap_Case=0603, Manufacturer=MuRata, Supplier Part Number 1=81-GRM188Z71A106MA3D, TempCo=X7R, Tolerance_%=20%, Value1=Unknown, Value2=10V, ValueDisplayed=10uF
C16: library part CMP-0007179-4, "CAP, CERM, 120 pF, 50 V, +/- 5%, C0G/NP0, 0603", Cap_Case=0603, Manufacturer=MuRata, Supplier Part Number 1=490-1429-1-ND, TempCo=C0G/NP0, Tolerance_%=5%, Value1=Unknown, Value2=50V, ValueDisplayed=120pF
C17 C18 C26 C27: library part CMP-0007158-5, "CAP, CERM, 22 uF, 10 V, +/- 20%, X5R, 0603", Cap_Case=0603, Manufacturer=MuRata, Supplier Part Number 1=490-13243-1-ND, TempCo=X5R, Tolerance_%=20%, Value1=Unknown, Value2=10V, ValueDisplayed=22uF
C19 C24: library part CMP-0008305-2, "CAP, CERM, 22 uF, 25 V, +/- 20%, X5R, 0805", Cap_Case=0805, Manufacturer=MuRata, Supplier Part Number 1=490-10749-1-ND, TempCo=X5R, Tolerance_%=20%, Value1=Unknown, Value2=25V, ValueDisplayed=22uF
C23: library part CMP-0007182-4, "CAP, CERM, 130 pF, 50 V, +/- 5%, C0G/NP0, 0603", Cap_Case=0603, Manufacturer=MuRata, Supplier Part Number 1=490-1430-1-ND, TempCo=C0G/NP0, Tolerance_%=5%, Value1=Unknown, Value2=50V, ValueDisplayed=130pF
C28 C30 C31 C32 C33 C34 C35 C36 C37 C45 C54 C57 C60 C61 C62 C63 C65: library part CMP-0006223-2, "CAP, CERM, 0.1 uF, 16 V, +/- 20%, X5R, 0402", Cap_Case=0402, Manufacturer="Wurth Elektronik", Supplier Part Number 1=40Y4445, TempCo=X5R, Tolerance_%=20%, Value1=Unknown, Value2=16V, ValueDisplayed=0.1uF
C29 C39 C40: library part CMP-0078625-1, "CAP, CERM, 1 µF, 25 V,+/- 20%, X5R, 0402", Cap_Case=0402, Manufacturer=MuRata, Supplier Part Number 1=490-10018-1-ND, TempCo=X5R, Tolerance_%=20%, Value2=25V, ValueDisplayed=1µF
C38 C46: library part CMP-0007691-2, "CAP, CERM, 10 uF, 10 V, +/- 10%, X7R, 0805", Cap_Case=0805, Manufacturer="Wurth Elektronik", Supplier Part Number 1=710-885012207026, TempCo=X7R, Tolerance_%=10%, Value1=Unknown, Value2=10V, ValueDisplayed=10uF
C41 C42 C43: library part CMP-0078265-1, "CAP, CERM, 0.22 µF, 16 V,+/- 10%, X7R, AEC-Q200 Grade 1, 0402", Cap_Case=0402, Manufacturer=MuRata, Supplier Part Number 1=490-10671-1-ND, TempCo=X7R, Tolerance_%=10%, Value2=16V, ValueDisplayed=0.22µF
C44 C53 C59 C64 C66: library part CMP-0064924-2, "CAP, CERM, 1 uF, 10 V,+/- 20%, X5R, 0402", Cap_Case=0402, Manufacturer="Wurth Elektronik", Supplier Part Number 1=732-7489-1-ND, TempCo=X5R, Tolerance_%=20%, Value1=Unknown, Value2=10V, ValueDisplayed=1uF
C47 C48 C49 C50 C51 C52 C79 C80 C93 C94 C101 C108 C112 C120 C126 C132 C154 C162 C177 C193 C194 C195 C196 C197 C198 C199 C200 C201 C202 C205 C206: library part CMP-0006629-2, "CAP, CERM, 0.1 uF, 10 V, +/- 10%, X7R, 0402", Cap_Case=0402, Manufacturer=MuRata, Supplier Part Number 1=GRM155R71A104KA01D-ND, TempCo=X7R, Tolerance_%=10%, Value1=Unknown, Value2=10V, ValueDisplayed=0.1uF
C55 C56 C203 C204: library part CMP-0064970-1, "CAP, CERM, 0.1 uF, 16 V,+/- 10%, X7R, 0201", Cap_Case=0201, Manufacturer=MuRata, Supplier Part Number 1=81-GRM033Z71C104KE4D, TempCo=X7R, Tolerance_%=10%, Value1=Unknown, Value2=16V, ValueDisplayed=0.1uF
C58: library part CMP-0007694-2, "CAP, CERM, 0.01 uF, 50 V, +/- 10%, X7R, 0805", Cap_Case=0805, Manufacturer="Wurth Elektronik", Supplier Part Number 1=732-8074-1-ND, TempCo=X7R, Tolerance_%=10%, Value1=Unknown, Value2=50V, ValueDisplayed=0.01uF
C67 C68 C69 C70 C71 C72 C73 C74 C75 C76 C77 C78 C81 C82 C83 C84 C85 C86 C87 C88 C89 C90 C91 C92 C95 C96 C97 C98 C99 C100 C102 C103 C104 C105 C106 C107: library part CMP-0006200-2, "CAP, CERM, 100 pF, 16 V, +/- 10%, X7R, 0402", Cap_Case=0402, Manufacturer=AVX, Supplier Part Number 1=478-7887-1-ND, TempCo=X7R, Tolerance_%=10%, Value1=Unknown, Value2=16V, ValueDisplayed=100pF
C109 C113 C116 C151 C155 C158: library part CMP-0008706-2, "CAP, CERM, 10 uF, 35 V, +/- 20%, X7R, 1206_190", Cap_Case=1206, Manufacturer=TDK, Supplier Part Number 1=445-8034-1-ND, TempCo=X7R, Tolerance_%=20%, Value1=Unknown, Value2=35V, ValueDisplayed=10uF
C110 C111 C114 C115 C117 C118 C119 C152 C153 C156 C157 C159 C160 C161 C174: library part CMP-0009670-3, "CAP, CERM, 0.1 uF, 16 V, +/- 10%, X5R, 0201", Cap_Case=0201, Manufacturer=MuRata, Supplier Part Number 1=490-10387-1-ND, TempCo=X5R, Tolerance_%=10%, Value1=Unknown, Value2=16V, ValueDisplayed=0.1uF
C121 C122 C123 C163 C164 C165: library part CMP-0006227-2, "CAP, CERM, 0.01 uF, 16 V, +/- 10%, X7R, 0402", Cap_Case=0402, Manufacturer="Wurth Elektronik", Supplier Part Number 1=710-885012205031, TempCo=X7R, Tolerance_%=10%, Value1=Unknown, Value2=16V, ValueDisplayed=0.01uF
C124 C125 C127 C128 C129 C130 C131 C166 C167 C168 C169 C170 C171 C172 C173: library part CMP-0064909-1, "CAP, CERM, 1 uF, 10 V,+/- 20%, X5R, 0201", Cap_Case=0201, Manufacturer=MuRata, Supplier Part Number 1=490-13226-1-ND, TempCo=X5R, Tolerance_%=20%, Value1=Unknown, Value2=10V, ValueDisplayed=1uF
C133 C134 C137 C140 C175 C176 C179 C182: library part CMP-0006641-2, "CAP, CERM, 0.1 uF, 16 V, +/- 10%, X7R, 0402", Cap_Case=0402, Manufacturer=MuRata, Supplier Part Number 1=490-3261-1-ND, TempCo=X7R, Tolerance_%=10%, Value1=Unknown, Value2=16V, ValueDisplayed=0.1uF
C135: library part CMP-0006292-2, "CAP, CERM, 0.01 uF, 16 V, +/- 10%, X7R, 0402", Cap_Case=0402, Manufacturer=TDK, Supplier Part Number 1=445-1262-1-ND, TempCo=X7R, Tolerance_%=10%, Value1="0.0623 ohm", Value2=16V, ValueDisplayed=0.01uF
C136 C139 C178 C181: library part CMP-0006221-2, "CAP, CERM, 0.1 uF, 10 V, +/- 20%, X5R, 0402", Cap_Case=0402, Manufacturer="Wurth Elektronik", Supplier Part Number 1=732-7487-1-ND, TempCo=X5R, Tolerance_%=20%, Value1=Unknown, Value2=10V, ValueDisplayed=0.1uF
C141 C183: library part CMP-0009436-2, "CAP, CERM, 1000 pF, 2000 V, +/- 10%, X7R, 1808", Cap_Case=1808, Manufacturer=MuRata, Supplier Part Number 1=490-8145-1-ND, TempCo=X7R, Tolerance_%=10%, Value1=Unknown, Value2=2000V, ValueDisplayed=1000pF
C142 C143 C144 C145 C146 C147 C148 C149 C184 C185 C186 C187 C188 C189 C190 C191: library part CMP-0009667-3, "CAP, CERM, 4.7 pF, 50 V, +/- 5%, C0G/NP0, 0201", Cap_Case=0201, Manufacturer=MuRata, Supplier Part Number 1=490-6130-1-ND, TempCo=C0G/NP0, Tolerance_%=5%, Value1=Unknown, Value2=50V, ValueDisplayed=4.7pF
C150: library part CMP-0009297-1, "CAP, CERM, 0.01 uF, 1500 V, +/- 10%, X7R, 1812", Cap_Case=1812, Manufacturer=AVX, Supplier Part Number 1=478-4735-1-ND, TempCo=X7R, Tolerance_%=10%, Value1="0.05 ohm", Value2=1500V, ValueDisplayed=0.01uF
D1 D2 D4 D5 D8 D9 D11: library part CMP-0081765-2, "LED, Green, SMD", Color=Green, Manufacturer="Wurth Elektronik", Power_TotalModule=99mW, Value1=0.099W, Value2=3.2V
D3: library part CMP-0005564-3, "Diode, TVS, Bi, 33 V, SMB", Manufacturer="Diodes Inc.", Value1=600W
D6 D7: library part CMP-0860710-3, "1-channel 30 kV ESD protection diode with low capacitance (< 1pF) in 0402 package, DPY0002A (X1SON-2)", Alternate Manufacturer="Texas Instruments", Operating Temperature Range="-40 to 125 C", Rating=Catalog
D10: library part CMP-0077018-2, "Diode, Schottky, 30 V, 0.2 A, SOT-523", Manufacturer="Diodes Inc.", Value1=0.2A, Value2=1V
D12 D13 D14 D15 D16 D17 D18 D19: library part CMP-0073609-3, "1-Channel ESD Protection Diode With Low Dynamic Resistance and Low Clamping Voltage, DPY0002A (X1SON-2)", Alternate Manufacturer="Texas Instruments", Alternate PartNumber=TPD1E1B04DPYT, Operating Temperature Range="-40 to 125 C", Rating=Catalog
D20 D21 D22: library part CMP-0081199-2, "Diode, Schottky, 30 V, 0.1 A, AEC-Q101, SOD-323", Manufacturer="Diodes Inc.", Value1=0.1A, Value2=1V
FID1 FID2 FID3 FID4 FID5 FID6: library part CMP-0077181-1, "Fiducial mark.  There is nothing to buy or mount.", Manufacturer=N/A
J1: library part CMP-0087130-1, Current_A=15A, Manufacturer="Phoenix Contact", Voltage_V=400V
J2: library part CMP-0086695-3, "USB - micro B USB 2.0 Receptacle Connector 5 Position Surface Mount, Right Angle; Through Hole", Current_A=3A, Manufacturer="Wurth Electronics", Voltage_V=30V
J3: library part CMP-0054801-2, "Header, 2.54 mm, 6x1, Gold, TH", Color=Black, Manufacturer="Wurth Elektronik", Supplier Part Number 1=732-5319-ND
J4: library part CMP-0054796-4, "Header, 2.54 mm, 3x1, Gold, TH", Manufacturer="Wurth Elektronik", Supplier Part Number 1=732-5316-ND
J5: library part CMP-0078832-1, "MicroSD Card Connector, R/A, Gold, SMT", Color=Black, Current_A=500mA, Manufacturer="Wurth Elektronik", Supplier Part Number 1=732-3819-1-ND, Voltage_V=100V
J6: library part CMP-0075640-2, "Header, 1.27mm, 10x2, Tin, SMT", Color=Black, Current_A=3.1A, Manufacturer=Samtec, Supplier Part Number 1=SAM8792-ND
J7 J9: library part CMP-0087236-1, "WR-MJ Modular Jack THR Horizontal Shielded w. LED and EMI Finger 8P8C Tab Up", Current_A=1.5A, Manufacturer="Wurth Electronics Inc.", Voltage_V=125V
J8: library part CMP-0078815-1, "Screw Terminal, R/A", Current_A=15A, Manufacturer=Keystone, Supplier Part Number 1=36-7781-ND
J11 J12 J13: library part CMP-0055585-1, "Header, 2.54mm, 25x2, Gold, TH", Color=Black, Manufacturer=Samtec, Supplier Part Number 1=SAM1040-25-ND
J14: library part CMP-0055593-1, "Header, 2.54mm, 9x2, Gold, TH", Color=Black, Current_A=6.3A, Manufacturer=Samtec, Supplier Part Number 1=56P2531, Voltage_V=550V
J15: library part CMP-0054603-1, "Header, 2.54mm, 6x1, Gold, TH", Color=Black, Current_A=3A, Manufacturer="Sullins Connector Solutions", Supplier Part Number 1=S1011E-06-ND
L1 L2: library part CMP-0096734-1, "470 nH Shielded - Inductor 8.5 A 8.1mOhm Max 1616 (4040 Metric) -", Digikey Part Number=732-744383560047HTCT-ND, Manufacturer=Wurth, Mouser Part Number=710-744383560047HT, Operating Temperature Range="-55°C to +150°C", Self Resonant Frequency=83MHz, Test Frequency=100kHz, Tolerance_%=30%
L3 L4 L5 L6 L7 L8 L9 L10 L11 L12: library part CMP-0003092-1, "Ferrite Bead, 80 ohm @ 100 MHz, 0.5 A, 0805", Manufacturer="Wurth Elektronik", Supplier Part Number 1=732-4645-1-ND, Value1="0.2 ohm", Value2=0.5A, ValueDisplayed="80 ohm"
LBL1: library part CMP-0003625-1, "Thermal Transfer Printable Labels, 0.650\" W x 0.200\" H - 10,000 per roll", Manufacturer=Brady, Supplier Part Number 1=97C5133
Logo2: library part CMP-0074847-1, "FCC_disclaimer"
Logo3: library part CMP-0074769-1
MD1: library part CMP-0120622-1, "Embedded Cortex®- R5F module based on TI AM243x for headless Applications with Real - time demand", Frequency_Fixed=800MHz, Manufacturer=TQ-Group, Max Supply Voltage=5.25V, Min Supply Voltage=4.75V, Operating Temperature Range="-40°C to +85°C"
NT1 NT2: library part CMP-0078142-4, "Single point connection between nets.", Manufacturer=N/A
NT4: library part CMP-0078142-5, "Single point connection between nets.", Manufacturer=N/A
Q1 Q2: library part CMP-0000665-1, "MOSFET, N-CH, 30 V, 15 A, PowerPAK SO-8", Alternate Manufacturer=None, Manufacturer=Vishay-Siliconix, Supplier Part Number 1=SI7892BDP-T1-E3CT-ND, Value1=0.005, Value2="27 nC"
Q3: library part CMP-0000198-1, "MOSFET, N-CH, 12 V, 2.9 A, YJC0003A (PICOSTAR-3)", Alternate Manufacturer=None, Manufacturer="Texas Instruments", Supplier Part Number 1=296-39991-1-ND, Value1=0.04, Value2="2 nC"
Q4 Q5 Q6 Q7: library part CMP-0000198-1, "MOSFET, N-CH, 12 V, 2.9 A, YJC0003A (PICOSTAR-3)", Alternate Manufacturer=None, Manufacturer="Texas Instruments", PartNumber=CSD13383F4, Supplier Part Number 1=296-39991-1-ND, Value1=0.04, Value2="2 nC"
R1: library part CMP-0025842-4, "RES, 68 k, 5%, 0.1 W, AEC-Q200 Grade 0, 0603", Manufacturer=Vishay-Dale, Power_W=100mW, Supplier Part Number 1=541-68KGCT-ND, TempCo="200 ppm/C", Tolerance_%=5%, Value2=0.1W, Value_Code=68k0, ValueDisplayed=68k
R2: library part CMP-0026365-1, "RES, 402 k, 1%, 0.063 W, 0402", Manufacturer=Vishay-Dale, Power_W=63mW, Supplier Part Number 1=541-402KLCT-ND, TempCo="100 ppm/C", Tolerance_%=1%, Value2=0.063W, Value_Code=402k
R3: library part CMP-0026367-2, "RES, 40.2 k, 1%, 0.063 W, AEC-Q200 Grade 0, 0402", Manufacturer=Vishay-Dale, Power_W=63mW, Supplier Part Number 1=541-40.2KLCT-ND, TempCo="100 ppm/C", Tolerance_%=1%, Value2=0.063W, Value_Code=40k2, ValueDisplayed=40.2k
R4: library part CMP-0025999-1, "RES, 133 k, 1%, 0.063 W, 0402", Manufacturer=Vishay-Dale, Power_W=63mW, Supplier Part Number 1=541-133KLCT-ND, TempCo="100 ppm/C", Tolerance_%=1%, Value2=0.063W, Value_Code=133k
R5 R10 R246 R260 R286 R305: library part CMP-0026822-3, "RES, 0, 5%, 0.063 W, AEC-Q200 Grade 0, 0402", Manufacturer=Vishay-Dale, Power_W=63mW, Supplier Part Number 1=541-0.0JCT-ND, TempCo="200 ppm/C", Tolerance_%=5%, Value2=0.063W, Value_Code=0000, ValueDisplayed=0
R6 R13 R19 R26 R35 R36 R37 R38 R39 R40 R41 R42 R51 R52 R53 R54 R55 R56 R57 R58 R59 R60 R62 R68 R69 R70 R71 R72 R83 R86 R87 R88 R253 R292 R296 R297 R298 R299 R300: library part CMP-0025958-3, "RES, 10.0 k, 1%, 0.063 W, AEC-Q200 Grade 0, 0402", Manufacturer=Vishay-Dale, Power_W=63mW, Supplier Part Number 1=541-10.0KLCT-ND, TempCo="100 ppm/C", Tolerance_%=1%, Value2=0.063W, Value_Code=10k0, ValueDisplayed=10.0k
R7 R64 R67: library part CMP-0026982-5, "RES, 8.2 k, 5%, 0.063 W, AEC-Q200 Grade 0, 0402", Manufacturer=Vishay-Dale, Power_W=63mW, Supplier Part Number 1=541-8.2KJCT-ND, TempCo="200 ppm/C", Tolerance_%=5%, Value2=0.063W, Value_Code=8k20, ValueDisplayed=8.2k
R8: library part CMP-0026003-3, "RES, 13.0 k, 1%, 0.063 W, AEC-Q200 Grade 0, 0402", Manufacturer=Vishay-Dale, Power_W=63mW, Supplier Part Number 1=541-13.0KLCT-ND, TempCo="100 ppm/C", Tolerance_%=1%, Value2=0.063W, Value_Code=13k0, ValueDisplayed=13.0k
R9: library part CMP-0026825-5, "RES, 10 k, 5%, 0.063 W, AEC-Q200 Grade 0, 0402", Manufacturer=Vishay-Dale, Power_W=63mW, Supplier Part Number 1=541-10KJCT-ND, TempCo="200 ppm/C", Tolerance_%=5%, Value2=0.063W, Value_Code=10k0, ValueDisplayed=10k
R11 R17 R18 R25: library part CMP-0025950-3, "RES, 100 k, 1%, 0.063 W, AEC-Q200 Grade 0, 0402", Manufacturer=Vishay-Dale, Power_W=63mW, Supplier Part Number 1=541-100KLCT-ND, TempCo="100 ppm/C", Tolerance_%=1%, Value2=0.063W, Value_Code=100k
R12: library part CMP-0026937-5, "RES, 4.3 k, 5%, 0.063 W, AEC-Q200 Grade 0, 0402", Manufacturer=Vishay-Dale, Power_W=63mW, Supplier Part Number 1=541-4.3KJCT-ND, TempCo="200 ppm/C", Tolerance_%=5%, Value2=0.063W, Value_Code=4k30, ValueDisplayed=4.3k
R14 R21 R91: library part CMP-0026918-5, "RES, 3.3 k, 5%, 0.063 W, AEC-Q200 Grade 0, 0402", Manufacturer=Vishay-Dale, Power_W=63mW, Supplier Part Number 1=541-3.3KJCT-ND, TempCo="200 ppm/C", Tolerance_%=5%, Value2=0.063W, Value_Code=3k30, ValueDisplayed=3.3k
R15: library part CMP-0026288-2, "RES, 316 k, 1%, 0.063 W, AEC-Q200 Grade 0, 0402", Manufacturer=Vishay-Dale, Power_W=63mW, Supplier Part Number 1=541-316KLCT-ND, TempCo="100 ppm/C", Tolerance_%=1%, Value2=0.063W, Value_Code=316k
R16: library part CMP-0026385-2, "RES, 453 k, 1%, 0.063 W, AEC-Q200 Grade 0, 0402", Manufacturer=Vishay-Dale, Power_W=63mW, Supplier Part Number 1=541-453KLCT-ND, TempCo="100 ppm/C", Tolerance_%=1%, Value2=0.063W, Value_Code=453k
R20: library part CMP-0026539-2, "RES, 73.2 k, 1%, 0.063 W, AEC-Q200 Grade 0, 0402", Manufacturer=Vishay-Dale, Power_W=63mW, Supplier Part Number 1=541-73.2KLCT-ND, TempCo="100 ppm/C", Tolerance_%=1%, Value2=0.063W, Value_Code=73k2, ValueDisplayed=73.2k
R22: library part CMP-0026403-2, "RES, 49.9 k, 1%, 0.063 W, AEC-Q200 Grade 0, 0402", Manufacturer=Vishay-Dale, Power_W=63mW, Supplier Part Number 1=541-49.9KLCT-ND, TempCo="100 ppm/C", Tolerance_%=1%, Value2=0.063W, Value_Code=49k9, ValueDisplayed=49.9k
R23: library part CMP-0026586-2, "RES, 88.7 k, 1%, 0.063 W, AEC-Q200 Grade 0, 0402", Manufacturer=Vishay-Dale, Power_W=63mW, Supplier Part Number 1=541-88.7KLCT-ND, TempCo="100 ppm/C", Tolerance_%=1%, Value2=0.063W, Value_Code=88k7, ValueDisplayed=88.7k
R24: library part CMP-0026158-2, "RES, 200 k, 1%, 0.063 W, AEC-Q200 Grade 0, 0402", Manufacturer=Vishay-Dale, Power_W=63mW, Supplier Part Number 1=541-200KLCT-ND, TempCo="100 ppm/C", Tolerance_%=1%, Value2=0.063W, Value_Code=200k
R27 R28 R29 R30 R31 R32 R33 R34 R43 R44 R45 R46 R47 R48 R49 R50 R73 R75 R77: library part CMP-0026071-3, "RES, 1.00 k, 1%, 0.063 W, AEC-Q200 Grade 0, 0402", Manufacturer=Vishay-Dale, Power_W=63mW, Supplier Part Number 1=541-1.00KLCT-ND, TempCo="100 ppm/C", Tolerance_%=1%, Value2=0.063W, Value_Code=1k00, ValueDisplayed=1.00k
R61 R63 R74 R76 R78 R79 R80 R81 R84 R85 R241 R268 R276 R281 R291 R306 R307 R309 R310 R317 R318 R319 R320 R321 R322 R323 R324 R325 R326 R327 R328 R329 R330 R331 R332 R333 R334 R335 R336 R337 R338 R339 R340 R341 R342 R343: library part CMP-0026992-3, "RES, 0, 5%, 0.1 W, AEC-Q200 Grade 0, 0402", Manufacturer=Panasonic, Power_W=100mW, Supplier Part Number 1=P0.0JCT-ND, TempCo="600 ppm/C", Tolerance_%=5%, Value2=0.1W, Value_Code=0000, ValueDisplayed=0
R65 R66 R92 R93 R94 R95 R96 R97 R98 R99 R100 R101 R102 R103 R104 R105 R106 R107 R108 R110 R111 R112 R113 R114 R115 R116 R117 R118 R119 R120 R121 R122 R123 R124 R125 R126 R127 R128 R133 R134 R135 R136 R137 R138 R139 R140 R141 R142 R143 R144 R161 R162 R163 R164 R165 R166 R167 R168 R169 R170 R171 R172 R187 R188 R189 R190 R191 R192 R201 R202 R203 R204 R205 R206 R220 R228 R230 R233 R234 R237 R238 R247 R270 R273 R274 R277 R278 R293 R294 R295 R301 R302 R303 R304: library part CMP-0026880-3, "RES, 22, 5%, 0.063 W, AEC-Q200 Grade 0, 0402", Manufacturer=Vishay-Dale, Power_W=63mW, Supplier Part Number 1=541-22JCT-ND, TempCo="200 ppm/C", Tolerance_%=5%, Value2=0.063W, Value_Code=22R0, ValueDisplayed=22
R82 R232 R239 R272 R279 R308: library part CMP-0026159-2, "RES, 200, 1%, 0.063 W, AEC-Q200 Grade 0, 0402", Manufacturer=Vishay-Dale, Power_W=63mW, Supplier Part Number 1=541-200LCT-ND, TempCo="100 ppm/C", Tolerance_%=1%, Value2=0.063W, Value_Code=200R, ValueDisplayed=200
R89 R90: library part CMP-0026934-3, "RES, 470, 5%, 0.063 W, AEC-Q200 Grade 0, 0402", Manufacturer=Vishay-Dale, Power_W=63mW, Supplier Part Number 1=541-470JCT-ND, TempCo="200 ppm/C", Tolerance_%=5%, Value2=0.063W, Value_Code=470R, ValueDisplayed=470
R109: library part CMP-0027004-2, "RES, 0, 5%, 0.063 W, 0402", Manufacturer="Yageo America", Power_W=63mW, Supplier Part Number 1=311-0.0JRCT-ND, TempCo="200 ppm/C", Tolerance_%=5%, Value2=0.063W, Value_Code=0000, ValueDisplayed=0
R129 R130 R131 R132 R145 R146 R147 R148 R149 R150 R151 R152 R153 R154 R155 R156 R157 R158 R159 R160 R173 R174 R175 R176 R177 R178 R179 R180 R181 R182 R183 R184 R185 R186 R193 R194 R195 R196 R197 R198 R199 R200 R207 R208 R209 R210 R211 R212: library part CMP-0026825-5, "RES, 10 k, 5%, 0.063 W, AEC-Q200 Grade 0, 0402", Manufacturer=Vishay-Dale, PartNumber=CRCW040210K0JNED, Power_W=63mW, Supplier Part Number 1=541-10KJCT-ND, TempCo="200 ppm/C", Tolerance_%=5%, Value2=0.063W, Value_Code=10k0, ValueDisplayed=10k
R213 R214 R215 R216 R217 R218 R219 R221 R222 R223 R224 R225 R226 R227 R254 R255 R256 R257 R258 R259 R261 R262 R263 R264 R265 R266 R267: library part CMP-0026237-2, "RES, 2.49 k, 1%, 0.063 W, AEC-Q200 Grade 0, 0402", Manufacturer=Vishay-Dale, Power_W=63mW, Supplier Part Number 1=541-2.49KLCT-ND, TempCo="100 ppm/C", Tolerance_%=1%, Value2=0.063W, Value_Code=2k49, ValueDisplayed=2.49k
